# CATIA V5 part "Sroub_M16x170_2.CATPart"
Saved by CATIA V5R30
Part number: Sroub_M16x170_2
Definition: E 1200_16x170_1
Nomenclature: E 1200_16x170_1
Source: Unknown
Description: PART--DESC
Bounding box of the stored display mesh (mm): x 128 to 152, y 125.01 to 148.99, z -259 to -73
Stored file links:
  E:\Bakalarka\Model\Forma_v7\Sroub_M16x170_2.CATPart
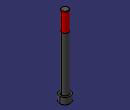
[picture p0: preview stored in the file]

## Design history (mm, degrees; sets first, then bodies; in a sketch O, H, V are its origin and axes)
Body1 "MANIFOLD_SOLID_BREP #3802" (main body)
  Solid1: solid without history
